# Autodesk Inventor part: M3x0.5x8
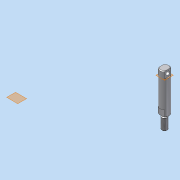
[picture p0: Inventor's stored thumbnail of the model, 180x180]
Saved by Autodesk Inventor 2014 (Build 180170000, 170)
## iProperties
Company: 한국ATC센터
Created: 2009-02
Part Number: M3x0.5x8
Document SubType Name: Modeling
Designer: KYOUNG IL JANG
Density: 2.71 g/cm^3
Material: 알루미늄-6061
Mass: 23.7345 g
Surface Area: 33.7774 cm^2
Volume: 8.75813 cm^3
Vendor: CBT Solutions
Appearance: 알루미늄 - 평지
Author: KYOUNG IL JANG
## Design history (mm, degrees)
node "작업 평면1"
sketch "스케치1"
  geometry: L1 (126.442, 94.902)-(135.988, 94.902); L2 (135.988, 94.902)-(135.988, 85.356); L3 (135.988, 85.356)-(126.442, 85.356); L4 (126.442, 85.356)-(126.442, 94.902); A1 r 6.75 centre (131.215, 90.129) between (126.442, 94.902) and (126.442, 85.356); A2 r 6.75 centre (131.215, 90.129) between (135.988, 94.902) and (126.442, 94.902); A3 r 6.75 centre (131.215, 90.129) between (135.988, 85.356) and (135.988, 94.902); A4 r 6.75 centre (131.215, 90.129) between (126.442, 85.356) and (135.988, 85.356); 2 further points
  constraints: 8 end point, 8 point on circle, 4 centre point, 2 coincident, 1 horizontal, 9 other
  dimensions: "d0" = 13.5 diameter of A1
extrude "돌출1" new body sketch "스케치1" distance "d1" = 60; taper "d2" = 0 deg
sketch "스케치2"
  geometry: C1 r 4 at (0, 0); 1 further point
  constraints: 1 centre point, 1 coincident
  dimensions: "d3" = 8 diameter of C1
extrude "돌출2" join sketch "스케치2" distance "d4" = 20; taper "d5" = 0 deg
sketch "스케치3"
  geometry: C1 r 4 at (0, 0) reference; C2 r 3 at (0, 0); 1 further point
  constraints: 1 centre point
  dimensions: "d6" = 1 radial gap between concentric circles of C1 C2
extrude "돌출3" cut sketch "스케치3" distance "d7" = 2; taper "d8" = 0 deg
chamfer "모따기1" distance "d9" = 1; stored, may be unused: second distance "d10" = 2, angle "d11" = 45 deg
feature "스레드1" dims "d12" = 10, "d13" = 0
chamfer "모따기2" distance "d14" = 1; stored, may be unused: second distance "d15" = 2, angle "d16" = 45 deg
extrude "돌출4" cut sketch "스케치1" distance "d18" = 10; taper "d19" = 0 deg
node "작업 평면2"
chamfer "모따기3" distance "d23" = 1; stored, may be unused: second distance "d24" = 2, angle "d25" = 45 deg
extrude "돌출5" cut sketch "스케치1" stored distance "d21" = 10; taper "d22" = 0 deg
sketch "스케치4"
  geometry: L1 (-10, 7.979)-(-10, 1.567) reference; 2 further points
  constraints: 1 horizontal alignment
  dimensions: "d26" = 5 distance from line of point (-5, 4.773) L1
hole "구멍1" sketch "스케치4" at (-5, 4.773) diameter "d27" = 5.5; stored, may be unused: countersink angle "d31" = 90 deg, drill point angle "d33" = 118 deg; dims "d28" = 6, "d29" = 4, "d30" = 2, "d32" = 8
node "솔리드1"
